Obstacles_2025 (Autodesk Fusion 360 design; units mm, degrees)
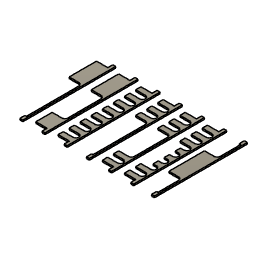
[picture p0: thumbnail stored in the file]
sketch "Sketch1" plane through (0, 0, 0) normal (0, 0, 1) x axis (1, 0, 0)
  line L1 (17.5, 0) -> (0, 0)
  line L2 (0, 48) -> (17.5, 48)
  line L3 (-17, 48) -> (0, 48)
  line L4 (-17, 38) -> (-17, 48)
  line L5 (0, 38) -> (-17, 38)
  line L6 (0, 48) -> (17.5, 48)
  line L7 (280, 48) -> (0, 48)
  line L8 (140, 22.6934) -> (140, 48)
  line L9 (297, 48) -> (280, 48)
  line L10 (297, 38) -> (297, 48)
  line L11 (280, 38) -> (297, 38)
  line L12 (0, 0) -> (0, 38)
  line L13 (55, 0) -> (37.5, 0)
  line L14 (92.5, 0) -> (92.5, 33)
  line L15 (92.5, 0) -> (75, 0)
  line L16 (0, 0) -> (0, 38)
  line L17 (102.5, 43) -> (112.5, 43)
  line L18 (130, 43) -> (150, 43)
  line L19 (167.5, 43) -> (187.5, 43)
  line L20 (205, 43) -> (225, 43)
  line L21 (225, 43) -> (102.5, 43)
  line L22 (92.5, 0) -> (0, 0)
  line L23 (280, 43) -> (280, 38)
  line L24 (280, 43) -> (225, 43)
  line L25 (280, 48) -> (0, 48)
  line L26 (280, 43) -> (225, 43)
  line L27 (225, 43) -> (102.5, 43)
  line L28 (280, 48) -> (0, 48)
  line L29 (297, 48) -> (280, 48)
  line L30 (0, 48) -> (17.5, 48)
  line L31 (92.5, 0) -> (75, 0)
  line L32 (0, 48) -> (17.5, 48)
  line L33 (205, 43) -> (225, 43)
  line L34 (92.5, 0) -> (0, 0)
  line L35 (0, 0) -> (0, 38)
  line L36 (92.5, 0) -> (0, 0)
  line L37 (92.5, 0) -> (75, 0)
  line L38 (280, 43) -> (280, 38)
  line L39 (225, 43) -> (102.5, 43)
  line L40 (225, 43) -> (102.5, 43)
  line L41 (130, 43) -> (150, 43)
  line L42 (280, 48) -> (0, 48)
  line L43 (-17, 48) -> (0, 48)
  line L44 (55, 0) -> (37.5, 0)
  line L45 (-17, 38) -> (-17, 48)
  line L46 (55, 0) -> (37.5, 0)
  line L47 (0, 38) -> (-17, 38)
  line L48 (0, 0) -> (0, 38)
  line L49 (0, 48) -> (17.5, 48)
  line L50 (167.5, 43) -> (187.5, 43)
  line L51 (280, 38) -> (297, 38)
  line L52 (0, 0) -> (0, 38)
  line L53 (0, 48) -> (17.5, 48)
  line L54 (167.5, 43) -> (187.5, 43)
  line L55 (297, 48) -> (280, 48)
  line L56 (205, 43) -> (225, 43)
  line L57 (102.5, 43) -> (112.5, 43)
  line L58 (140, 22.6934) -> (140, 48)
  line L59 (92.5, 0) -> (92.5, 33)
  line L60 (-17, 48) -> (0, 48)
  line L61 (92.5, 0) -> (92.5, 33)
  line L62 (205, 43) -> (225, 43)
  line L63 (297, 48) -> (280, 48)
  line L64 (17.5, 0) -> (0, 0)
  line L65 (140, 22.6934) -> (140, 48)
  line L66 (92.5, 0) -> (75, 0)
  line L67 (130, 43) -> (150, 43)
  line L68 (0, 38) -> (-17, 38)
  line L69 (280, 43) -> (225, 43)
  line L70 (0, 38) -> (-17, 38)
  line L71 (55, 0) -> (37.5, 0)
  line L72 (280, 38) -> (297, 38)
  line L73 (17.5, 0) -> (0, 0)
  line L74 (297, 38) -> (297, 48)
  line L75 (102.5, 43) -> (112.5, 43)
  line L76 (-17, 38) -> (-17, 48)
  line L77 (297, 38) -> (297, 48)
  line L78 (140, 22.6934) -> (140, 48)
  line L79 (-17, 48) -> (0, 48)
  line L80 (102.5, 43) -> (112.5, 43)
  line L81 (92.5, 0) -> (92.5, 33)
  line L82 (280, 38) -> (297, 38)
  line L83 (0, 0) -> (0, 38)
  line L84 (17.5, 0) -> (0, 0)
  line L85 (167.5, 43) -> (187.5, 43)
  line L86 (0, 48) -> (17.5, 48)
  line L87 (280, 43) -> (280, 38)
  line L88 (0, 0) -> (0, 38)
  line L89 (-17, 38) -> (-17, 48)
  line L90 (0, 48) -> (17.5, 48)
  line L91 (297, 38) -> (297, 48)
  line L92 (0, 0) -> (0, 38)
  line L93 (92.5, 0) -> (0, 0)
  line L94 (130, 43) -> (150, 43)
  line L95 (280, 123) -> (0, 123)
  line L96 (280, 118) -> (225, 118)
  line L97 (215, 118) -> (102.5, 118)
  line L98 (280, 123) -> (0, 123)
  line L99 (242.5, 75) -> (225, 75)
  line L100 (297, 123) -> (280, 123)
  line L101 (0, 123) -> (17.5, 123)
  line L102 (92.5, 75) -> (75, 75)
  line L103 (280, 75) -> (225, 75)
  line L104 (0, 123) -> (17.5, 123)
  line L105 (205, 118) -> (225, 118)
  line L106 (92.5, 75) -> (0, 75)
  line L107 (0, 75) -> (0, 113)
  line L108 (92.5, 75) -> (0, 75)
  line L109 (92.5, 75) -> (75, 75)
  line L110 (280, 118) -> (280, 113)
  line L111 (225, 75) -> (225, 108)
  line L112 (225, 118) -> (102.5, 118)
  line L113 (225, 118) -> (102.5, 118)
  line L114 (130, 118) -> (150, 118)
  line L115 (280, 123) -> (0, 123)
  line L116 (-17, 123) -> (0, 123)
  line L117 (55, 75) -> (37.5, 75)
  line L118 (-17, 113) -> (-17, 123)
  line L119 (55, 75) -> (37.5, 75)
  line L120 (0, 113) -> (-17, 113)
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  point P1 (0, 0)
  point P2 (0, 0)
  point P11 (140, 48)
  point P5 (0, 48)
  point P13 (280, 48)
  point P6 (-17, 48)
  point P14 (297, 48)
  point P7 (-17, 38)
  point P15 (297, 38)
  point P8 (0, 38)
  point P16 (280, 38)
  point P28 (0, 0)
  point P92 (0, 0)
  point P101 (0, 0)
  point P115 (140, 48)
  point P95 (0, 48)
  point P113 (280, 48)
  point P106 (-17, 48)
  point P114 (297, 48)
  point P100 (297, 38)
  point P107 (-17, 38)
  point P63 (280, 38)
  point P108 (0, 38)
  point P103 (0, 0)
  point P71 (0, 0)
  point P90 (0, 0)
  point P75 (140, 48)
  point P30 (0, 48)
  point P96 (280, 48)
  point P65 (-17, 48)
  point P99 (297, 48)
  point P91 (-17, 38)
  point P97 (297, 38)
  point P85 (280, 38)
  point P89 (0, 38)
  point P86 (0, 0)
  point P44 (0, 0)
  point P58 (0, 0)
  point P39 (140, 48)
  point P36 (280, 48)
  point P38 (0, 48)
  point P33 (297, 48)
  point P47 (-17, 48)
  point P34 (297, 38)
  point P59 (-17, 38)
  point P37 (280, 38)
  point P57 (0, 38)
  point P54 (0, 0)
  point P181 (0, 75)
  point P190 (0, 75)
  point P205 (140, 123)
  point P192 (0, 75)
  point P160 (0, 75)
  point P179 (0, 75)
  point P164 (140, 123)
  point P175 (0, 75)
  point P130 (0, 75)
  point P144 (0, 75)
  point P125 (140, 123)
  point P140 (0, 75)
  point P206 (0, 150)
  point P212 (0, 150)
  point P265 (0, 225)
  point P267 (0, 225)
  point P296 (0, 300)
  point P300 (0, 300)
  point P274 (17.5, 343)
  point P278 (17.5, 343)
  point P333 (0, 375)
  point P334 (0, 375)
  point P314 (17.5, 418)
  point P315 (17.5, 418)
  point P356 (27.5, 418)
  point P359 (27.5, 418)
  point P361 (65, 418)
  point P364 (65, 418)
  point P368 (102.5, 418)
  point P371 (102.5, 418)
  point P373 (140, 418)
  point P377 (140, 418)
  point P379 (177.5, 418)
  point P382 (177.5, 418)
  point P385 (215, 418)
  point P388 (215, 418)
  point P392 (252.5, 418)
  point P395 (252.5, 418)
  point P398 (27.5, 343)
  point P401 (27.5, 343)
  point P403 (65, 343)
  point P407 (65, 343)
  point P410 (252.5, 343)
  point P413 (252.5, 343)
  point P416 (65, 268)
  point P418 (65, 268)
  point P422 (27.5, 268)
  point P424 (27.5, 268)
  point P428 (27.5, 193)
  point P431 (27.5, 193)
  point P434 (65, 193)
  point P437 (65, 193)
  point P439 (102.5, 193)
  point P442 (102.5, 193)
  point P446 (140, 193)
  point P448 (140, 193)
  point P451 (177.5, 193)
  point P455 (177.5, 193)
  point P458 (215, 193)
  point P461 (215, 193)
  point P464 (252.5, 193)
  point P467 (252.5, 193)
  point P139 (225, 118)
  point P158 (225, 118)
  point P3 (17.5, 0)
  point P10 (280, 48)
  point P93 (17.5, 0)
  point P68 (280, 48)
  point P76 (17.5, 0)
  point P98 (280, 48)
  point P46 (17.5, 0)
  point P35 (280, 48)
  point P182 (17.5, 75)
  point P184 (0, 123)
  point P195 (-17, 123)
  point P197 (0, 113)
  point P155 (280, 123)
  point P165 (17.5, 75)
  point P116 (0, 123)
  point P152 (-17, 123)
  point P178 (0, 113)
  point P187 (280, 123)
  point P132 (17.5, 75)
  point P124 (0, 123)
  point P133 (-17, 123)
  point P143 (0, 113)
  point P121 (280, 123)
  point P207 (17.5, 150)
  point P232 (0, 198)
  point P208 (-17, 198)
  point P210 (0, 188)
  point P227 (280, 198)
  point P258 (17.5, 225)
  point P237 (0, 273)
  point P262 (-17, 273)
  point P260 (0, 263)
  point P264 (280, 273)
  point P301 (17.5, 300)
  point P298 (0, 348)
  point P295 (-17, 348)
  point P289 (0, 338)
  point P270 (280, 348)
  point P329 (17.5, 375)
  point P307 (0, 423)
  point P311 (-17, 423)
  point P319 (0, 413)
  point P331 (280, 423)
  point P346 (0, 493)
  point P353 (0, 445)
  point P338 (-17, 493)
  point P336 (0, 483)
  point P339 (0, 488)
  horizontal L1
  horizontal L2
  coincident P1 P2
  horizontal L3
  vertical L4
  horizontal L5
  horizontal L6
  horizontal L7
  midpoint L7 P11
  symmetric P5 L8 P13
  symmetric P6 L8 P14
  symmetric P7 L8 P15
  symmetric P8 L8 P16
  coincident P1 P28
  perpendicular L14 L22
  perpendicular L7 L23
  perpendicular L23 L24
  horizontal L84
  horizontal L30
  coincident P92 P101
  horizontal L79
  vertical L76
  horizontal L70
  horizontal L32
  horizontal L25
  midpoint P115 L25
  symmetric P95 P113 L58
  symmetric P106 P114 L58
  symmetric P100 P107 L58
  symmetric P63 P108 L58
  coincident P101 P103
  perpendicular L36 L59
  horizontal L73
  horizontal L90
  coincident P71 P90
  horizontal L60
  vertical L45
  horizontal L68
  horizontal L86
  horizontal L28
  midpoint P75 L28
  symmetric P30 P96 L78
  symmetric P65 P99 L78
  symmetric P91 P97 L78
  symmetric P85 P89 L78
  coincident P86 P90
  perpendicular L34 L81
  perpendicular L28 L38
  perpendicular L26 L38
  horizontal L64
  horizontal L53
  coincident P44 P58
  horizontal L43
  vertical L89
  horizontal L47
  horizontal L49
  horizontal L42
  midpoint P39 L42
  symmetric P36 P38 L65
  symmetric P33 P47 L65
  symmetric P34 P59 L65
  symmetric P37 P57 L65
  coincident P54 P58
  perpendicular L61 L93
  perpendicular L42 L87
  perpendicular L69 L87
  horizontal L101
  coincident P181 P190
  horizontal L104
  horizontal L95
  midpoint P205 L95
  perpendicular L111 L113
  coincident P190 P192
  coincident P160 P179
  vertical L118
  horizontal L98
  midpoint P164 L98
  coincident P175 P179
  perpendicular L98 L110
  perpendicular L96 L110
  coincident P130 P144
  horizontal L116
  horizontal L120
  horizontal L115
  midpoint P125 L115
  coincident P140 P144
  coincident P206 P212
  coincident P265 P267
  coincident P296 P300
  coincident P274 P278
  coincident P333 P334
  coincident P314 P315
  coincident P356 P359
  coincident P361 P364
  coincident P368 P371
  coincident P373 P377
  coincident P379 P382
  coincident P385 P388
  coincident P392 P395
  coincident P398 P401
  coincident P403 P407
  coincident P410 P413
  coincident P416 P418
  coincident P422 P424
  coincident P428 P431
  coincident P434 P437
  coincident P439 P442
  coincident P446 P448
  coincident P451 P455
  coincident P458 P461
  coincident P464 P467
  coincident P139 L97
  coincident P158 L111
  dimension "d1" distance P2 P3 = 17.5
  dimension "d2" distance P2 P5 = 48
  dimension "d3" distance P5 P6 = 17
  dimension "d4" distance P5 P8 = 10
  dimension "d5" distance P5 P10 = 280
  dimension "d14" distance P92 P93 = 17.5
  dimension "d15" distance P92 P95 = 48
  dimension "d16" distance P95 P106 = 17
  dimension "d17" distance P95 P108 = 10
  dimension "d18" distance P68 P95 = 280
  dimension "d19" distance P71 P76 = 17.5
  dimension "d20" distance P30 P71 = 48
  dimension "d21" distance P30 P65 = 17
  dimension "d22" distance P30 P89 = 10
  dimension "d23" distance P30 P98 = 280
  dimension "d24" distance P44 P46 = 17.5
  dimension "d25" distance P38 P44 = 48
  dimension "d26" distance P38 P47 = 17
  dimension "d27" distance P38 P57 = 10
  dimension "d28" distance P35 P38 = 280
  dimension "d29" distance P181 P182 = 17.5
  dimension "d30" distance P181 P184 = 48
  dimension "d31" distance P184 P195 = 17
  dimension "d32" distance P184 P197 = 10
  dimension "d33" distance P155 P184 = 280
  dimension "d34" distance P160 P165 = 17.5
  dimension "d35" distance P116 P160 = 48
  dimension "d36" distance P116 P152 = 17
  dimension "d37" distance P116 P178 = 10
  dimension "d38" distance P116 P187 = 280
  dimension "d39" distance P130 P132 = 17.5
  dimension "d40" distance P124 P130 = 48
  dimension "d41" distance P124 P133 = 17
  dimension "d42" distance P124 P143 = 10
  dimension "d43" distance P121 P124 = 280
  dimension "d46" distance P206 P207 = 17.5
  dimension "d47" distance P206 P232 = 48
  dimension "d48" distance P208 P232 = 17
  dimension "d49" distance P210 P232 = 10
  dimension "d50" distance P227 P232 = 280
  dimension "d53" distance P258 P265 = 17.5
  dimension "d54" distance P237 P265 = 48
  dimension "d55" distance P237 P262 = 17
  dimension "d56" distance P237 P260 = 10
  dimension "d57" distance P237 P264 = 280
  dimension "d58" distance P300 P301 = 17.5
  dimension "d59" distance P298 P300 = 48
  dimension "d60" distance P295 P298 = 17
  dimension "d61" distance P289 P298 = 10
  dimension "d62" distance P270 P298 = 280
  dimension "d67" distance P329 P333 = 17.5
  dimension "d68" distance P307 P333 = 48
  dimension "d69" distance P307 P311 = 17
  dimension "d70" distance P307 P319 = 10
  dimension "d71" distance P307 P331 = 280
  dimension "d80" distance P346 P353 = 48
  dimension "d81" distance P338 P346 = 17
  dimension "d82" distance P336 P346 = 10
  dimension "d83" distance P339 P346 = 5
  dimension "d93" radius = 10
  dimension "d3" = 17
  dimension "d95" radius = 10
  dimension "d3" = 17
  dimension "d97" radius = 10
  dimension "d98" radius = 10
  dimension "d99" radius = 10
  dimension "d100" radius = 10
  dimension "d3" = 17
  dimension "d94" radius = 10
  dimension "d96" radius = 10
  dimension "d101" radius = 10
extrude "Extrude4" new body sketch "Sketch1" along normal blind 5
extrude "Extrude3" new body sketch "Sketch1" along normal blind 5
extrude "Extrude2" new body sketch "Sketch1" profile of L1 L2 L16 L3 L4 L5 L6 L7 L20 L9 L10 L11 L12 L13 L14 L15 L21 L22 L23 L24 along normal blind 5
extrude "Extrude5" new body sketch "Sketch1" along normal blind 5
extrude "Extrude6" new body sketch "Sketch1" along normal blind 5
extrude "Extrude7" new body sketch "Sketch1" along normal blind 5
extrude "Extrude9" new body sketch "Sketch1" along normal blind 5
move "Déplacer"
